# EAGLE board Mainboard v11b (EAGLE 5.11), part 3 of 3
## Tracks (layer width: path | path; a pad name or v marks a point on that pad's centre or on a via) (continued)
N$121  (via drill 0.3) (continued)
  Bottom 0.203: v56.33,75.43 54.59,77.17 50.3,77.17 v50.14,77.33
N$122  (via drill 0.3)
  Top 0.203: IC11.8 50.52,77.75 v50.14,78.13 | E12.4 56.93,75.63 v56.02,76.54
  Bottom 0.203: v50.14,78.13 50.46,77.81 54.75,77.81 v56.02,76.54
N$123
  Top 0.406: R31.1 78.23,120.83 80.46,123.05 LED3.AG
N$124  (via drill 0.3)
  Top 0.203: DISPLAY.1 28.87,17.48 29.19,17.8 v29.82,17.8 | v49.83,27.01 50.78,27.01 51.09,27.33 51.09,28.6 50.74,28.95 E13.7
  Bottom 0.203: v29.82,17.8 29.82,18.76 33.95,22.88 43.48,22.88 47.6,27.01 v49.83,27.01
N$125  (via drill 0.3)
  Top 0.203: DISPLAY.40 77.13,21.93 v75.86,21.93 | v69.51,41.3 69.86,41.65 E14.1
  Bottom 0.203: v75.86,21.93 65.54,21.93 61.26,26.22 61.26,33.99 68.56,41.3 v69.51,41.3
N$126  (via drill 0.3)
  Top 0.203: DISPLAY.38 74.59,22.56 v73.32,22.56 | v70.14,40.66 70.26,40.78 E14.3
  Bottom 0.203: v73.32,22.56 65.54,22.56 61.73,26.38 61.73,33.84 68.56,40.66 v70.14,40.66
N$127
  Top 0.203: C73.1 35.61,80.7 IC21.42
N$128
  Top 0.203: IC21.43 36.11,81.69 37.12,80.67 C73.2
N$130
  Top 0.203: IC21.18 36.11,94.2 R42.2
N$131
  Top 0.203: IC21.16 37.11,93.61 R41.2 C72.1
N$132  (via drill 0.3)
  Top 0.203: IC21.23 33.61,90.64 33.31,90.35 32.84,90.35 v32.2,90.99 | v30.46,94.32 31.35,94.32 R43.2 R40.1
  Bottom 0.203: v32.2,90.99 32.2,92.57 v30.46,94.32
N$133
  Top 0.203: IC21.20 35.11,93.74 R39.1
N$134
  Top 0.203: IC21.40 34.61,81.96 34.59,81.94 34.59,81.62 33,80.03 33,79.61 C68.1
N$135
  Top 0.406: R30.1 86.47,128 LED3.AR
N$136
  Top 0.203: E6.4 9.7,42.77 7.92,40.99 MSL.P$3
N$137
  Top 0.203: E6.6 9.3,43 8.54,42.24 MSL.P$4
N$138
  Top 0.203: E6.8 5.73,43.41 MSL.P$5
N$139
  Top 0.406: MSL.P$6 5.64,46.07 L9.2
N$140
  Top 0.406: Q8.3 28.23,121.62 26.65,123.21 24.27,123.21 R28.2
N$141
  Top 0.203: E19.4 40.97,79.11 42.05,80.19 42.05,85.75 41.21,86.59 IC21.5
N$142
  Top 0.203: IC21.6 41.32,87.09 42.52,85.88 42.52,80.03 41.37,78.88 E19.6
N$143
  Top 0.203: IC21.14 38.11,92.6 38.39,92.89 40.14,92.89 43.48,89.56 43.48,79.72 42.17,78.41 E19.10
N$144
  Top 0.203: IC21.9 40.17,88.61 41.57,88.61 43,87.18 43,79.87 41.77,78.64 E19.8
N$145
  Top 0.203: IC21.2 41.12,85.09 41.57,84.64 41.57,80.35 40.57,79.35 E19.2
N$146
  Top 0.406: Q10.3 87.14,121.95 R30.2
N$147
  Top 0.406: Q11.3 75.71,120.35 R31.2
N$149
  Top 0.203: IC25.42 35.92,27.65 C82.1
N$150
  Top 0.203: C82.2 37.28,27.65 37.28,27.8 36.81,28.28 36.65,28.44 36.42,28.66 IC25.43
N$152
  Top 0.203: IC25.18 36.42,41.02 R48.2
N$153
  Top 0.203: IC25.16 37.42,40.33 38.39,41.3 C81.1 R47.2
N$154  (via drill 0.3)
  Top 0.203: IC25.23 33.92,37.3 33.79,37.17 33,37.17 32.68,37.49 v32.68,38.12 | v31.09,41.3 31.94,41.3 R49.2 32.15,41.3 33.53,41.3 R46.1
  Bottom 0.203: v32.68,38.12 32.68,40.34 31.73,41.3 v31.09,41.3
N$155
  Top 0.203: IC25.20 35.42,41.2 R45.1
N$156
  Top 0.203: IC25.40 34.92,28.46 32.52,26.06 C77.1
N$163  (via drill 0.3)
  Top 0.203: IC25.5 41.69,33.24 v41.89,33.04 | v41.41,38.92 41.45,38.96 E20.8
  Bottom 0.203: v41.89,33.04 41.89,37.65 41.41,38.12 v41.41,38.92
N$164  (via drill 0.3)
  Top 0.203: IC25.6 42.27,33.74 v42.52,33.99 | v42.05,38.28 42.32,38.56 E20.6
  Bottom 0.203: v42.52,33.99 42.52,37.8 v42.05,38.28
N$165
  Top 0.203: IC25.14 38.42,39.26 38.87,39.71 41.41,39.71 41.76,39.36 E20.10
N$166
  Top 0.203: IC25.9 42.19,35.24 42.68,35.74 42.68,37.96 42.88,38.16 E20.4
N$167
  Top 0.203: E20.2 43.48,37.76 43.48,33.68 41.54,31.74 IC25.2
N$171
  Top 0.203: IC29.42 70.39,36.5 C91.1
N$172
  Top 0.203: IC29.43 69.89,35.3 C91.2
N$174
  Top 0.203: IC29.18 69.89,24.06 69.19,23.36 66.18,23.36 63.16,26.38 R54.2 62.42,26.06
N$175
  Top 0.203: IC29.16 68.89,24.33 68.4,23.84 66.34,23.84 62.52,27.65 62.42,27.65 C90.1 R53.2
N$176  (via drill 0.3)
  Top 0.203: IC29.23 72.39,26.56 72.53,26.69 73.32,26.69 73.64,26.38 v73.64,25.1 | v62.84,33.04 R52.1 R55.2
  Bottom 0.203: v73.64,25.1 73,24.47 64.91,24.47 62.68,26.69 62.68,29.39 63.48,30.19 63.48,32.41 v62.84,33.04
N$177  (via drill 0.3)
  Top 0.203: IC29.20 70.89,23.95 v70.78,23.84 | v62.84,31.14 62.42,31.14 R51.1
  Bottom 0.203: v70.78,23.84 64.91,23.84 62.21,26.53 62.21,30.5 v62.84,31.14
N$178
  Top 0.203: IC29.40 71.39,35.4 73,37.01 73,37.59 C86.1
N$185
  Top 0.203: E21.10 66.37,39.27 64.11,37.01 64.11,31.3 64.79,30.62 IC29.5
N$186
  Top 0.203: IC29.6 64.66,30.12 63.64,31.14 63.64,37.17 65.97,39.5 E21.12
N$187  (via drill 0.3)
  Top 0.203: IC29.14 67.89,26.56 67.76,26.69 66.97,26.69 66.65,26.38 v66.65,25.74 | E21.4 67.57,38.25 v67.45,38.12
  Bottom 0.203: v66.65,25.74 64.91,25.74 63.64,27.01 63.64,29.07 67.45,32.88 v67.45,38.12
N$188  (via drill 0.3)
  Top 0.203: IC29.9 64.41,28.62 v64.27,28.76 | E21.2 67.97,39.5 v68.24,39.23
  Bottom 0.203: v64.27,28.76 64.27,29.07 68.24,33.04 v68.24,39.23
N$189
  Top 0.203: E21.8 66.77,39.03 64.59,36.85 64.59,32.25 64.72,32.12 IC29.2
N$191  (via drill 0.3)
  Top 0.203: IC33.44 30.25,100.56 v30.77,100.03 | E23.4 38.51,100.23 38.24,100.51 v36.49,100.51
  Bottom 0.203: v36.49,100.51 31.25,100.51 v30.77,100.03
N$192
  Top 0.203: E1.2 11.12,64.83 10.14,63.84 KD.9
N$193
  Top 0.203: IC33.42 29.25,98.96 C100.1
N$194
  Top 0.203: 30.77,98.92 C100.2 30.93,98.92 29.75,100.1 IC33.43
N$196
  Top 0.203: 30.07,112.75 R60.2 29.75,112.93 IC33.18
N$197
  Top 0.203: R59.2 C99.1 30.75,112.34 IC33.16
N$198  (via drill 0.3)
  Top 0.203: IC33.23 27.25,111.33 26.96,111.62 25.22,111.62 v25.06,111.47 | v23.79,113.69 24.69,113.69 R61.2 R58.1
  Bottom 0.203: v23.79,113.69 23.79,112.73 v25.06,111.47
N$199
  Top 0.203: IC33.20 28.75,112.06 28.23,112.58 28.23,113.31 R57.1
N$200
  Top 0.203: IC33.40 28.25,100.85 27.28,99.88 27.28,99.46 C95.1
N$201
  Top 0.203: E1.4 8.03,65.23 KD.10
N$202
  Top 0.203: E1.6 10.57,65.63 9.82,66.38 KD.11
N$203
  Top 0.203: E1.8 10.81,66.03 9.19,67.65 KD.12
N$204
  Top 0.203: E3.2 11.12,69.91 10.14,68.92 KD.13
N$205
  Top 0.203: E3.4 8.03,70.31 KD.14
N$206
  Top 0.203: E3.6 10.89,70.71 10.14,71.46 KD.15
N$207
  Top 0.203: E23.8 39.31,101.34 35.34,105.32 IC33.5
N$208
  Top 0.203: E22.2 41.61,100.16 41.25,100.51 40.78,100.51 35.47,105.82 IC33.6
N$209
  Top 0.203: IC33.14 31.75,111.33 32.05,111.62 34.43,111.62 35.54,110.51 37.76,110.51 38.39,109.88 38.39,108.29 38.39,107.97 38.39,104.8 41.25,101.94 41.73,101.94 42.8,100.86 E22.8
N$210
  Top 0.203: 33.83,107.34 IC33.9 35.24,107.32 41.09,101.46 41.57,101.46 42.41,100.63 E22.6
N$211
  Top 0.203: E23.6 38.91,101.11 36.2,103.82 IC33.2
N$213
  Top 0.203: E22.4 42.01,100.39 41.41,100.99 40.94,100.99 35.61,106.32 IC33.7
N$214
  Top 0.203: E3.8 11.12,71.11 9.5,72.73 KD.16
PDN  (via drill 0.3)
  Top 0.203: IC3.8 102.98,108.31 v102.85,108.45 | v44.43,52.41 44.43,51.77 42.9,50.25 IC15.26 | v60.14,67.81 67.13,67.81 v68.88,69.56
  Bottom 0.203: v68.88,69.56 69.51,70.19 69.51,71.3 64.43,76.38 64.43,78.92 70.46,84.95 70.46,89.08 73.95,92.57 73.95,102.26 75.86,104.16 84.91,104.16 89.99,104.16 93.96,104.16 95.55,105.75 100.15,105.75 v102.85,108.45 | v44.43,52.41 47.6,52.41 48.08,52.89 48.71,52.89 50.14,54.31 50.78,54.31 56.97,60.51 56.97,63.52 60.14,66.7 v60.14,67.81
SD_CD
  Top 0.203: IC15.91 64.02,54.25 64.11,54.16 70.78,54.16 71.06,54.43 E7.5
SD_CK  (via drill 0.3)
  Top 0.203: IC15.113 59.12,61.85 59.51,61.46 59.51,54.79 v61.57,52.73 | v70.78,55.9 71.45,56.57 E8.7
  Bottom 0.203: v61.57,52.73 66.02,52.73 67.29,54 68.88,54 v70.78,55.9
SD_CMD  (via drill 0.3)
  Top 0.203: IC15.116 57.62,65.44 57.92,65.75 61.73,65.75 62.37,65.11 62.37,63.84 60.94,62.41 60.94,57.65 v61.57,57.01 | v68.88,56.54 69.19,56.86 70.78,56.86 70.9,56.97 E8.5
  Bottom 0.203: v61.57,57.01 62.37,56.22 68.56,56.22 v68.88,56.54
SD_D0  (via drill 0.3)
  Top 0.203: IC15.98 61.63,57.75 v61.57,57.81 | v65.7,57.81 67.61,57.81 68.24,57.17 68.24,55.9 68.91,55.23 E7.1
  Bottom 0.203: v65.7,57.81 v61.57,57.81
SD_D1  (via drill 0.3)
  Top 0.203: IC15.99 61.93,58.25 v61.57,58.6 | v67.45,57.17 67.45,55.74 68.36,54.83 E7.3
  Bottom 0.203: v61.57,58.6 61.73,58.44 66.18,58.44 v67.45,57.17
SD_D2  (via drill 0.3)
  Top 0.203: IC15.111 60.12,62.12 60.46,61.78 60.46,55.43 v61.57,54.31 | v69.51,58.12 70.78,58.12 71.13,57.77 E8.1
  Bottom 0.203: v61.57,54.31 62.84,55.59 68.88,55.59 69.51,56.22 v69.51,58.12
SD_D3  (via drill 0.3)
  Top 0.203: IC15.112 59.62,61.99 59.98,61.62 59.98,55.11 v61.57,53.52 | v70.14,57.49 70.26,57.37 E8.3
  Bottom 0.203: v61.57,53.52 66.18,53.52 67.29,54.63 68.56,54.63 70.14,56.22 v70.14,57.49
SD_PWR  (via drill 0.3)
  Top 0.203: IC15.102 61.92,59.75 v61.57,59.39 | v77.13,57.49 78.72,57.49 78.72,56.86 R22.1 79.25,57.81 IC10.4
  Bottom 0.203: v61.57,59.39 61.89,59.08 75.54,59.08 v77.13,57.49
SD_WP
  Top 0.203: IC15.90 63.89,53.75 63.95,53.68 71.1,53.68 71.45,54.03 E7.7
SPI2_MISO  (via drill 0.3)
  Top 0.203: v26.33,17.8 26.33,15.58 25.98,15.23 E11.3 | IC15.28 42.67,49.25 43.16,48.76 43.16,47.33 43.48,47.01 44.9,47.01 v45.54,46.38
  Bottom 0.203: v45.54,46.38 46.97,44.95 47.76,44.16 47.76,32.88 40.14,25.26 39.82,25.26 39.03,24.47 33,24.47 v26.33,17.8
SPI2_MOSI  (via drill 0.3)
  Top 0.203: v25.7,17.17 25.7,15.9 25.58,15.78 E11.5 | IC15.29 42.53,48.75 42.68,48.6 42.68,47.17 43.48,46.38 v44.74,46.38
  Bottom 0.203: v44.74,46.38 46.49,44.63 47.28,43.84 47.28,33.04 39.98,25.74 33.63,25.74 26.33,18.44 26.01,18.44 25.7,18.12 v25.7,17.17
SPI2_SCK  (via drill 0.3)
  Top 0.203: IC15.117 57.12,61.76 56.49,61.14 v56.49,47.65 | v25.06,16.53 25.06,15.9 25.18,15.78 E11.7
  Bottom 0.203: v56.49,47.65 55.86,47.65 54.27,46.06 49.83,46.06 48.24,44.47 48.24,32.73 40.3,24.79 39.98,24.79 39.19,23.99 33.16,23.99 27.28,18.12 27.28,17.8 26.01,16.53 v25.06,16.53
SPI4_MISO  (via drill 0.3)
  Top 0.203: v49.83,35.9 49.83,33.68 49.94,33.56 E13.4 | v50.78,44.79 50.78,45.11 51.09,45.42 v51.09,52.57 51.09,54.63 44.43,61.3 42.68,61.3 42.63,61.25 IC15.4 40.41,61.25 40.3,61.14 35.06,61.14 34.59,60.66 28.87,60.66 15.85,47.65 10.77,47.65 9.7,46.58 E6.3 | E5.3 97.97,45.47 v98.24,45.74
  Bottom 0.203: v49.83,35.9 49.83,37.8 50.3,38.28 50.3,44.31 v50.78,44.79 | v98.24,45.74 | v98.24,45.74 97.61,46.38 96.18,46.38 95.23,45.42 70.78,45.42 65.86,50.35 63,50.35 62.21,51.14 60.94,51.14 59.35,52.73 51.25,52.73 v51.09,52.57
SPI4_MOSI  (via drill 0.3)
  Top 0.203: v49.19,36.53 49.19,33.36 49.54,33.01 E13.2 | v50.14,45.42 50.14,45.74 50.46,46.06 v50.46,53.2 50.46,54.63 44.27,60.82 42.84,60.82 42.76,60.75 IC15.5 40.53,60.75 40.46,60.66 35.54,60.66 34.9,60.03 28.87,60.03 15.85,47.01 v11.09,47.01 | E5.7 97.17,45.11 v96.66,45.11 | v8.55,47.01 8.9,46.66 E6.7
  Bottom 0.203: v49.19,36.53 49.19,38.12 48.87,38.44 48.87,44.16 v50.14,45.42 | v50.46,53.2 59.51,53.2 61.1,51.62 62.37,51.62 63.16,50.82 66.02,50.82 70.78,46.06 95.23,46.06 96.18,47.01 97.77,47.01 98.88,45.9 98.88,45.58 98.4,45.11 v96.66,45.11 | v11.09,47.01 v8.55,47.01
SPI4_SCK  (via drill 0.3)
  Top 0.203: v50.46,35.27 50.46,33.68 50.34,33.56 E13.6 | E5.5 97.57,45.47 v97.29,45.74 | v51.73,45.42 v51.73,51.93 51.73,54.63 43.63,62.73 42.47,62.73 42.45,62.75 IC15.1 41.08,62.75 40.94,62.89 39.35,62.89 38.08,61.62 34.59,61.62 34.27,61.3 28.87,61.3 15.85,48.28 10.77,48.28 9.3,46.81 E6.5
  Bottom 0.203: v50.46,35.27 50.46,37.49 50.78,37.8 50.78,43.84 51.73,44.79 v51.73,45.42 | v97.29,45.74 96.18,45.74 95.23,44.79 70.46,44.79 66.18,49.08 63.64,49.08 62.05,50.66 60.78,50.66 59.19,52.25 52.05,52.25 v51.73,51.93
SPI6_MISO  (via drill 0.3)
  Top 0.203: E2.3 75.98,102.46 v75.86,102.58 | 54.59,68.13 56.33,68.13 58.24,66.22 68.4,66.22 v68.88,66.7 | 54.59,68.13 54.59,68.92 56.53,70.86 E12.1 | IC15.127 52.12,65.34 52.68,65.9 52.68,68.13 | 52.68,68.13 52.68,68.28 51.09,69.87 43.48,69.87 41.25,67.65 40.94,67.33 39.03,65.43 38.71,65.43 38.08,64.79 Q2.3 | 54.59,68.13 52.68,68.13
  Bottom 0.203: v68.88,66.7 70.78,68.6 70.78,71.3 65.38,76.7 65.38,78.6 71.41,84.64 71.41,87.65 74.91,91.14 74.91,101.62 v75.86,102.58
SPI6_MOSI  (via drill 0.3)
  Top 0.203: E2.5 76.14,102.06 v75.86,101.78 | v51.73,62.41 51.12,63.03 IC15.129 51.12,65.61 51.73,66.22 51.73,67.97 50.78,68.92 43.79,68.92 39.35,64.47 39.03,64.47 38.39,63.84 32.36,63.84 v32.05,63.52 | v71.41,68.6 68.88,68.6 67.45,67.17 58.56,67.17 56.97,68.76 v56.97,68.92 57.73,69.68 E12.7 | E1.7 13.59,66.03 13.63,66.06 v19.34,66.06
  Bottom 0.203: v51.73,62.41 51.89,62.25 53.32,62.25 53.95,62.89 53.95,64.47 56.97,67.49 v56.97,68.92 | v71.41,68.6 71.41,71.3 65.86,76.86 65.86,78.44 71.89,84.48 71.89,87.49 75.38,90.99 75.38,101.31 v75.86,101.78 | v32.05,63.52 29.19,66.38 19.98,66.38 19.66,66.06 v19.34,66.06
SPI6_SCK  (via drill 0.3)
  Top 0.203: E2.1 76.85,102.86 v76.5,103.21 | v52.05,63.2 51.62,63.64 IC15.128 51.62,65.47 52.21,66.06 52.21,68.13 50.94,69.4 43.63,69.4 39.19,64.95 38.87,64.95 38.24,64.32 30.62,64.32 v30.46,64.16 | v68.88,67.65 67.92,66.7 58.4,66.7 56.33,68.76 v56.02,68.76 57.33,70.07 E12.5 | E1.3 13.83,65.23 14.27,64.79 v19.34,64.79
  Bottom 0.203: v76.5,103.21 75.54,103.21 74.43,102.1 74.43,92.41 70.94,88.92 70.94,84.8 64.91,78.76 64.91,76.54 70.14,71.3 70.14,68.92 v68.88,67.65 | v56.02,68.76 55.54,68.28 55.54,66.7 53.48,64.63 53.48,63.2 53,62.73 52.52,62.73 v52.05,63.2 | v52.05,63.2 | v30.46,64.16 19.98,64.16 v19.34,64.79
SQI1_CS  (via drill 0.3)
  Top 0.203: IC15.136 47.62,63.53 v47.44,63.36 | v31.73,54.95 IC9.1
  Bottom 0.203: v47.44,63.36 47.6,63.2 47.6,57.01 44.27,53.68 33,53.68 v31.73,54.95
SQI1_MISO  (via drill 0.3)
  Top 0.203: IC15.21 40.32,52.75 v39.98,52.41 | v30.46,54.95 IC9.2
  Bottom 0.203: v39.98,52.41 39.66,52.73 32.05,52.73 30.46,54.31 v30.46,54.95
SQI1_MOSI
  Top 0.203: IC15.20 39.14,53.25 38.87,53.52 38.87,54.79 38.24,54.79 37.44,55.59 33.95,55.59 32.68,54.31 32.68,48.28 32.36,47.97 28.87,47.97 27.92,48.92 IC9.5
SQI_CLK  (via drill 0.3)
  Top 0.203: IC15.48 49.12,45.98 49.83,46.7 v49.83,47.97 | v29.19,51.14 IC9.6
  Bottom 0.203: v29.19,51.14 32.05,48.28 36.81,48.28 37.12,48.6 37.76,48.6 38.08,48.28 40.3,48.28 40.78,48.76 44.74,48.76 45.54,47.97 v49.83,47.97
SRST  (via drill 0.3)
  Top 0.203: v43.16,51.77 43.16,51.14 42.77,50.75 IC15.25 38.58,50.75 C41.1 38.13,50.56 36.43,48.86 R27.1 36.33,47.49 34.9,46.06 26.96,46.06 v24.11,48.92 | v48.08,94.48 47.13,94.48 43.48,98.13 43.48,100.99 43.79,101.31 43.79,103.84 43.5,104.14 IC14.29 | RESET.1 3.29,20.66 v5.69,20.66 | v59.19,73.68 61.26,75.75 v61.26,77.02 60.42,77.85 E9.3
  Bottom 0.203: v43.16,51.77 47.6,51.77 48.24,52.41 48.87,52.41 50.3,53.84 50.94,53.84 57.45,60.35 57.45,63.36 61.41,67.33 61.41,71.46 v59.19,73.68 | v24.11,48.92 3.47,48.92 0.61,46.06 0.61,25.74 v5.69,20.66 | v61.26,77.02 60.62,77.65 60.62,81.94 54.59,87.97 54.59,92.73 52.84,94.48 v48.08,94.48
SW2
  pour Top (no thermals): 65.7,95.27 59.67,95.27 59.35,94.95 59.35,92.73 62.52,92.73 64.43,94.64 65.38,94.64 65.7,94.64
TIM1_CH1
  Top 0.203: IC15.100 63.94,58.75 64.59,59.39 66.02,59.39 67.61,60.98 67.61,62.57 68.08,63.05 69.03,63.05 69.39,63.41 E16.3
TIM1_CH2
  Top 0.203: IC15.101 63.81,59.25 64.43,59.87 65.86,59.87 66.97,60.98 66.97,62.57 67.92,63.52 68.88,63.52 69.16,63.8 E16.1
TIM2_CH1  (via drill 0.3)
  Top 0.203: IC15.41 45.62,44.39 47.92,46.7 v47.92,56.38 | E22.3 42.01,97.54 43.48,96.07 43.48,94 v44.11,93.37 | v47.92,56.38
  Bottom 0.203: v44.11,93.37 44.43,93.05 44.43,82.1 47.28,79.24 47.28,67.17 48.08,66.38 48.08,56.54 v47.92,56.38 | v47.92,56.38
TIM3_CH1  (via drill 0.3)
  Top 0.203: v30.77,61.94 28.55,61.94 26.53,59.91 E18.5 | IC15.42 46.12,44.25 48.55,46.7 v48.55,54.63
  Bottom 0.203: v30.77,61.94 31.09,61.62 31.09,54.63 32.52,53.2 44.59,53.2 45.06,53.68 47.6,53.68 v48.55,54.63
TIM3_CH2
  Top 0.203: IC15.135 48.08,64.66 48.08,65.59 47.6,66.06 47.6,67.33 46.49,68.44 43.95,68.44 39.51,64 39.19,64 38.55,63.36 33.31,63.36 32.84,62.89 28.62,62.89 26.05,60.31 E18.7
TIM4_CH1  (via drill 0.3)
  Top 0.203: IC15.81 62.98,49.23 v61.73,49.23 | E18.3 23.99,59.51 24.43,59.08 v24.43,58.12
  Bottom 0.203: v24.43,58.12 24.74,58.12 32.36,50.5 40.3,50.5 40.62,50.19 48.08,50.19 48.71,50.82 52.05,50.82 52.52,51.3 58.87,51.3 60.94,49.23 v61.73,49.23
TIM4_CH2  (via drill 0.3)
  Top 0.203: IC15.82 62.01,49.75 v61.73,50.03 | E18.1 23.12,59.11 23.47,58.76 v23.79,58.76
  Bottom 0.203: v23.79,58.76 24.74,58.76 32.52,50.98 40.46,50.98 40.78,50.66 47.92,50.66 48.55,51.3 51.89,51.3 52.37,51.77 59.03,51.77 60.78,50.03 v61.73,50.03
TIM5_CH1  (via drill 0.3)
  Top 0.203: IC15.34 41.77,46.22 42.68,46.22 43.16,45.74 45.7,45.74 46.65,46.7 46.65,56.7 45.38,57.97 v43.95,59.39 | E19.9 42.17,75.46 v42.84,74.79
  Bottom 0.203: v43.95,59.39 41.41,61.94 41.41,68.76 42.84,70.19 v42.84,74.79
TIM5_CH2  (via drill 0.3)
  Top 0.203: IC15.35 42.52,45.75 43,45.27 45.86,45.27 47.28,46.7 v47.28,54.31 | E17.9 65.66,73.72 66.18,73.21 66.18,71.94 63.95,69.71 v60.62,69.71
  Bottom 0.203: v47.28,54.31 | v47.28,54.31 49.19,56.22 51.41,56.22 56.02,60.82 56.02,63.84 59.03,66.86 59.03,68.6 59.35,68.92 59.83,68.92 v60.62,69.71
TIM5_CH3  (via drill 0.3)
  Top 0.203: IC15.36 41.57,45.25 41.57,44.47 v42.52,43.52 | E20.9 45.34,39.36 45.7,39.71 v45.7,39.87
  Bottom 0.203: v45.7,39.87 45.7,40.98 43.16,43.52 v42.52,43.52
TIM5_CH4  (via drill 0.3)
  Top 0.203: 43.62,42.89 IC15.37 43.62,44.3 v43.95,44.63 | E21.3 67.57,42.37 v67.76,42.57
  Bottom 0.203: v43.95,44.63 44.11,44.79 44.11,46.54 44.59,47.01 45.7,47.01 46.02,46.7 54.27,46.7 55.86,48.28 57.92,48.28 60.94,45.27 60.94,44.79 63.16,42.57 v67.76,42.57
TIM8_CH1  (via drill 0.3)
  Top 0.203: IC15.96 63.85,56.75 65.54,58.44 66.49,58.44 v68.24,60.19 | E16.5 69.63,63.01 68.88,62.25 v68.24,62.25
  Bottom 0.203: v68.24,60.19 | v68.24,60.19 v68.24,62.25
TIM8_CH2
  Top 0.203: IC15.97 63.71,57.25 65.38,58.92 66.18,58.92 68.88,61.62 | E16.7 69.86,62.61 68.88,61.62 | 68.88,61.62
TIM10_CH1  (via drill 0.3)
  Top 0.203: R21.2 69.83,48.06 Q4.1 69.51,50.36 v69.51,51.46 | IC15.139 46.12,63.74 47.13,62.73 49.03,62.73 52.37,59.39 v52.37,53.84
  Bottom 0.203: v52.37,53.84 52.52,53.68 59.67,53.68 61.26,52.09 68.88,52.09 v69.51,51.46
TIM11_CH1  (via drill 0.3)
  Top 0.203: E22.7 42.8,98.01 44.74,96.07 v44.74,94.95 | IC15.140 45.62,63.29 v46.49,62.41
  Bottom 0.203: v44.74,94.95 43.79,94.95 43.48,94.64 43.48,92.73 43.95,92.26 43.95,81.94 46.81,79.08 46.81,62.73 v46.49,62.41
TIM12_CH1  (via drill 0.3)
  Top 0.203: IC15.75 61.76,46.25 v61.73,46.22 | E3.3 13.51,70.31 13.95,69.87 v13.95,68.6 13.71,68.36 RN1.4
  Bottom 0.203: v61.73,46.22 61.41,46.22 58.4,49.23 55.54,49.23 54.91,48.6 49.19,48.6 49.03,48.44 45.7,48.44 44.9,49.23 40.62,49.23 40.14,48.76 38.24,48.76 37.92,49.08 36.97,49.08 36.65,48.76 32.84,48.76 29.19,52.41 25.38,52.41 13.95,63.84 v13.95,68.6
TIM12_CH2  (via drill 0.3)
  Top 0.203: IC15.76 62.16,46.75 v61.73,47.17 | E3.5 13.75,70.71 15.53,68.92 v15.53,68.6 15.53,67.86 RN1.1
  Bottom 0.203: v61.73,47.17 61.1,47.17 58.56,49.71 55.38,49.71 54.75,49.08 49.03,49.08 48.87,48.92 45.86,48.92 45.06,49.71 40.46,49.71 39.98,49.23 38.39,49.23 38.08,49.55 36.81,49.55 36.49,49.23 33,49.23 29.19,53.05 25.7,53.05 15.38,63.36 15.38,68.44 v15.53,68.6
TIM14_CH1  (via drill 0.3)
  Top 0.203: IC15.43 46.62,44.12 47.92,45.42 49.19,46.7 v49.19,51.93 | v12.99,69.24 12.99,69.91 E3.1
  Bottom 0.203: v12.99,69.24 15.85,69.24 17.44,67.65 17.44,65.11 19.98,62.57 28.55,62.57 29.82,61.3 29.82,54.31 32.68,51.46 40.62,51.46 40.94,51.14 47.6,51.14 48.4,51.93 v49.19,51.93
TP_CS
  Top 0.203: IC15.89 63.03,53.2 66.34,53.2 68.88,50.66 68.88,47.01 71.06,44.83 E14.8
TP_IRQ
  Top 0.203: IC15.50 50.12,41.59 48.71,40.19 48.71,38.28 51.09,35.9 51.09,33.36 50.74,33.01 E13.8
UART8_RX  (via drill 0.3)
  Top 0.203: v49.35,61.3 46.81,61.3 45.12,62.99 IC15.141 | E10.3 57.4,77.85 v57.45,77.81
  Bottom 0.203: v49.35,61.3 49.83,61.78 49.83,68.6 50.14,68.92 52.37,68.92 57.45,74 v57.45,77.81
UART8_TX  (via drill 0.3)
  Top 0.203: v48.71,60.66 46.81,60.66 44.62,62.86 IC15.142 | E10.1 57,78.76 v56.17,78.76
  Bottom 0.203: v48.71,60.66 48.71,61.46 49.35,62.09 49.35,68.76 49.98,69.4 52.21,69.4 56.97,74.16 56.97,77.49 56.17,78.29 v56.17,78.76
USART3_RX  (via drill 0.3)
  Top 0.203: IC15.70 60.12,44.34 58.87,45.58 v58.87,59.39 | E15.12 48.98,91.67 v49.19,91.46
  Bottom 0.203: v58.87,59.39 59.03,59.55 59.03,63.68 61.57,66.22 62.05,66.7 62.37,67.02 62.37,71.94 58.72,75.59 58.72,79.08 58.4,79.4 58.4,81.62 57.92,82.1 | 57.92,82.1 | 57.92,82.1 51.41,88.61 51.41,90.51 50.46,91.46 v49.19,91.46
USART3_TX  (via drill 0.3)
  Top 0.203: IC15.69 59.62,44.21 58.4,45.42 58.4,46.7 58.24,46.85 v58.24,58.76 | v50.78,90.19 50.78,90.83 49.38,92.22 E15.10
  Bottom 0.203: v58.24,58.76 58.24,59.71 58.56,60.03 58.56,63.84 60.94,66.22 61.41,66.7 61.57,66.86 61.89,67.17 61.89,71.78 58.24,75.43 58.24,78.92 57.92,79.24 57.92,81.46 56.97,82.41 | 56.97,82.41 | 56.97,82.41 50.78,88.61 v50.78,90.19
USB-5V
  Top 0.305: IC8.1 72.63,107.97 C18.1 70.47,107.87 USB.1
USB_DM  (via drill 0.3)
  Top 0.203: IC15.103 61.67,60.25 v61.57,60.19 | v72.69,103.69 72.69,104.48 71.13,106.03 E4.7
  Bottom 0.203: v61.57,60.19 61.73,60.19 64.27,60.19 68.24,64.16 68.24,71.3 63.48,76.06 63.48,79.24 65.7,81.46 65.7,86.86 72.05,93.21 72.05,103.05 v72.69,103.69
USB_DP  (via drill 0.3)
  Top 0.203: IC15.104 61.81,60.75 v61.57,60.98 | v72.05,104.32 71.54,104.83 E4.1
  Bottom 0.203: v61.57,60.98 64.43,60.98 67.76,64.32 67.76,71.14 66.02,72.89 | 66.02,72.89 63,75.91 63,79.4 65.22,81.62 65.22,87.02 71.57,93.37 71.57,103.84 v72.05,104.32 | 66.02,72.89
USB_EN  (via drill 0.3)
  Top 0.203: IC15.125 53.12,65.54 53.48,65.9 v53.48,66.38 | IC8.4 76.5,104.9 R18.2 76.08,103.74 74.91,102.58 74.91,94.32 70.78,90.19 69.19,90.19 66.97,87.97 66.97,86.06 65.06,84.16 65.06,82.73 63.32,80.98 | 63.32,80.98 | 63.32,80.98 62.84,80.51 62.84,75.43 62.37,74.95 62.37,74.48 59.03,71.14 v58.4,71.14
  Bottom 0.203: v53.48,66.38 53.48,67.81 56.81,71.14 v58.4,71.14
VCC  (via drill 0.3)
  Top 0.203: C76.1 21.89,42.44 | IC25.24 33.42,38.92 v31.73,38.92 | IC29.24 72.89,24.47 74.91,24.47 v75.22,24.79 | IC21.24 33.11,92.1 v31.41,92.1 | IC33.24 26.75,110.51 v26.01,110.51 | IC33.45 30.75,100.85 31.89,99.72 31.89,98.29 31.25,97.65 | C93.1 31.25,97.65 | 31.25,97.65 31.41,97.5 v32.2,97.5 | 37.76,25.95 C75.1 37.92,26.06 | 69.03,38.34 C84.1 | IC17.24 74.48,76.54 v78.4,76.54 | 70.3,89.24 C57.1 | v69.35,88.29 | v69.35,88.29 | 82.84,110.68 R5.2 82.84,110.99 84.91,110.99 85.07,110.83 IC1.5 | 69.83,87.02
  Top 0.305: IC25.45 37.42,28.62 37.76,28.28 38.39,28.28 38.55,28.12 38.55,26.69 37.92,26.06 | IC29.45 68.89,35.24 68.56,35.58 67.92,35.58 67.61,35.9 67.61,37.07 C84.1 | C66.1 v38.39,79.08 38.39,81.46 38.24,81.62 37.44,81.62 37.11,81.96 IC21.45 | 37.76,25.95 v37.76,25.1 | v69.03,39.08 69.03,38.34 | IC17.45 70.48,86.68 70.14,87.02 69.83,87.02 69.67,87.18 69.67,88.29 | 69.67,88.29 69.67,88.61 70.3,89.24 | 69.67,88.29 v69.35,88.29
  Top 0.406: IC5.2 IC5.1 70.14,93.69 69.19,92.73 v67.61,92.73
  Top 0.61: v49.67,81.78 49.67,83.18 EXT.10
  Bottom 0.203: v31.41,92.1 30.46,93.05 v19.98,93.05 | v13.63,114.96 21.57,114.96 22.84,113.69 22.84,112.73 25.06,110.51 v26.01,110.51 | v31.73,38.92 28.55,41.93 v19.66,41.93 | v75.22,24.79 76.5,23.52 v86.34,23.52 | v78.4,76.54 84.43,76.54 v86.34,78.44
  other vias: 62.37,101.46 62.37,102.26 19.98,94 19.19,93.05 19.19,94 19.66,42.89 18.87,41.93 18.87,42.89 87.13,23.52 87.13,22.56 86.34,22.56 87.13,78.44 87.13,79.24 13.63,115.91 12.84,114.96 12.84,115.91 13.31,60.35 13.31,61.3 14.26,61.3 14.26,60.35 85.54,78.44 79.67,111.78 79.67,110.19 81.26,110.19 79.67,110.99 81.26,110.99 80.46,111.78 81.26,111.78 80.46,110.19 80.46,110.99
  pour Top (no thermals): 19.66,76.54 19.98,76.22 22.84,76.22 23.16,76.54 23.16,94 22.84,94.32 19.03,94.32 18.71,94 18.71,93.05 19.03,92.73 21.57,92.73 21.89,92.41 21.89,89.88 21.57,89.56 19.98,89.56 19.66,89.24 19.66,87.97 19.98,87.65 21.57,87.65 21.89,87.34 21.89,84.16 21.57,83.84 19.98,83.84 19.66,83.53 19.66,82.25 19.98,81.94 21.57,81.94 21.89,81.62 21.89,78.44 21.57,78.13 19.98,78.13 19.66,77.81
  pour Top (no thermals): 13.31,98.45 13.63,98.13 16.49,98.13 16.8,98.45 16.8,115.91 16.49,116.23 12.68,116.23 12.36,115.91 12.36,114.96 12.68,114.64 15.22,114.64 15.53,114.32 15.53,111.78 15.22,111.47 13.63,111.47 13.31,111.15 13.31,109.88 13.63,109.56 15.22,109.56 15.53,109.24 15.53,106.07 15.22,105.75 13.63,105.75 13.31,105.43 13.31,104.16 13.63,103.84 15.22,103.84 15.53,103.53 15.53,100.35 15.22,100.03 13.63,100.03 13.31,99.72
  pour Top (no thermals): 19.34,25.42 19.66,25.1 22.52,25.1 22.84,25.42 22.84,42.89 22.52,43.2 18.71,43.2 18.39,42.89 18.39,41.93 18.71,41.62 21.25,41.62 21.57,41.3 21.57,38.76 21.25,38.44 19.66,38.44 19.34,38.12 19.34,36.85 19.66,36.53 21.25,36.53 21.57,36.22 21.57,33.04 21.25,32.73 19.66,32.73 19.34,32.41 19.34,31.14 19.66,30.82 21.25,30.82 21.57,30.5 21.57,27.33 21.25,27.01 19.66,27.01 19.34,26.69
  pour Top (no thermals): 86.66,40.03 86.34,40.34 83.48,40.34 83.16,40.03 83.16,22.56 83.48,22.25 87.29,22.25 87.61,22.56 87.61,23.52 87.29,23.84 84.75,23.84 84.43,24.15 84.43,26.69 84.75,27.01 86.34,27.01 86.66,27.33 86.66,28.6 86.34,28.91 84.75,28.91 84.43,29.23 84.43,32.41 84.75,32.73 86.34,32.73 86.66,33.04 86.66,34.31 86.34,34.63 84.75,34.63 84.43,34.95 84.43,38.12 84.75,38.44 86.34,38.44 86.66,38.76
  pour Top (no thermals): 87.92,96.54 87.61,96.86 84.75,96.86 84.43,96.54 84.43,79.08 85.38,78.13 87.29,78.13 87.61,78.44 87.61,79.4 87.29,79.72 86.66,79.72 85.7,80.67 85.7,83.21 86.02,83.53 87.61,83.53 87.92,83.84 87.92,85.11 87.61,85.43 86.02,85.43 85.7,85.75 85.7,88.92 86.02,89.24 87.61,89.24 87.92,89.56 87.92,90.83 87.61,91.14 86.02,91.14 85.7,91.46 85.7,94.64 86.02,94.95 87.61,94.95 87.92,95.27
  pour Supply (isolate 0.203, rank 6, no thermals): 2.2,118.45 2.2,23.2 105.07,23.2 105.07,118.45
  pour Top (no thermals): 1.56,61.94 5.06,61.94 5.69,61.3 11.09,61.3 11.41,61.62 14.27,61.62 14.58,61.3 14.58,60.35 14.27,60.03 12.99,58.76 5.69,58.76 5.06,58.12 1.56,58.12
  pour Top (no thermals): 65.7,95.91 63.16,95.91 62.84,96.22 62.84,100.67 62.21,101.31 62.21,102.26 62.84,102.89 64.43,102.89 64.43,100.99 65.7,99.72 65.7,98.77 65.38,98.45 64.43,98.45 63.8,97.81 63.8,97.18 64.43,96.54 65.7,96.54
  pour Top (no thermals): 83.48,109.88 79.67,109.88 79.35,110.19 79.35,111.78 79.67,112.1 83.16,112.1 83.48,111.78
VCC-SRC  (via drill 0.3)
  Top 0.203: R5.1 83.64,113.37 83.64,112.1 84.27,111.47 85.38,111.47 85.7,111.15 85.7,110.27 IC1.4 | v93.64,107.66 93.64,105.27 94.28,104.64 94.28,103.21 94.91,102.58 R8.2
  Top 0.305: IC2.11 94.74,107.97 93.96,107.97 v93.64,107.66
  Bottom 0.305: v93.64,107.66 93.96,107.97 93.96,108.29 87.29,114.96 v86.81,114.96
  pour Top (no thermals): 86.34,116.55 83.8,116.55 81.89,114.64 81.89,113.05 86.34,113.05 86.97,113.69 86.97,115.91
WF_CE  (via drill 0.3)
  Top 0.203: IC15.49 49.62,41.72 48.24,40.34 48.24,36.85 v46.17,34.79 | v23.79,16.85 23.79,15.58 24.38,14.99 E11.11
  Bottom 0.203: v23.79,16.85 25.85,18.91 26.17,18.91 33.47,26.22 39.82,26.22 46.17,32.57 v46.17,34.79
WF_CS  (via drill 0.3)
  Top 0.203: IC15.40 45.12,44.37 v44.9,44.63 | v25.7,19.71 25.7,18.12 24.43,16.85 24.43,15.74 24.78,15.39 E11.9
  Bottom 0.203: v44.9,44.63 44.9,44.47 46.81,42.57 46.81,36.38 45.54,35.11 45.54,32.57 39.66,26.69 33.31,26.69 26.33,19.71 v25.7,19.71
WF_IRQ  (via drill 0.3)
  Top 0.203: IC15.47 48.62,41.99 47.76,41.14 47.76,38.28 v45.22,35.74 | v26.96,21.3 26.96,15.58 26.38,14.99 E11.1
  Bottom 0.203: v26.96,21.3 27.28,21.3 33.16,27.17 39.51,27.17 45.06,32.73 45.06,35.58 v45.22,35.74
(copper drawn outside any net)
  shapes: Supply circle x6

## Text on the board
tPlace: IR TX | IR RX | Design: A.Ryll | Mainboard v11b | TIGERs Mannheim | MSL | MSR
